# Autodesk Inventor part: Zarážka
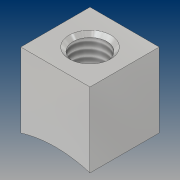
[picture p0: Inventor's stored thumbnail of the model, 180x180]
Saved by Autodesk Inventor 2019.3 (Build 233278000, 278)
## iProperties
Created: 2019-04
Part Number: Zarážka
Material: Hliník 6061-AHC
Document SubType Name: Modeling
Designer: B-hon
Density: 2.7 g/cm^3
Appearance: Hliník – tmavý
Author: B-hon
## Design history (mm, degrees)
sketch "Náčrt1"
  geometry: L1 (30, 0)-(30, 15); L2 (30, 15)-(0, 15); L3 (0, 15)-(0, 0); L4 (0, 0)-(2.958, 0); L5 (27.042, 0)-(30, 0); A1 r 17 centre (15, -12) between (27.042, 0) and (2.958, 0)
  constraints: 10 end point, 3 parallel, 2 horizontal, 2 perpendicular, 2 point on circle, 1 centre point
  dimensions: "d0" = 34 diameter of A1; "d1" = 30 distance of L1.end L2.end; "d2" = 15 distance from line of L3 A1.centre; "d4" = 15 distance of L2.end L3.end; "d16" = 12 distance from line of A1.centre L5
extrude "Vysunutí1" new body sketch "Náčrt1" distance "d5" = 10; taper "d6" = 0 deg
sketch "Náčrt2"
  geometry: L1 (0, 0)-(0, -10) reference; L2 (30, -10)-(0, -10) reference; 1 further point
  dimensions: "d14" = 15 distance from line of L1 point (15, -5); "d15" = 5 distance from line of L2 point (15, -5)
hole "Díra1" sketch "Náčrt2" at (15, -5) diameter "d7" = 4.917; stored, may be unused: countersink angle "d11" = 90 deg, drill point angle "d13" = 118 deg; dims "d8" = 12, "d9" = 6, "d10" = 2, "d12" = 17.1
sketch "Náčrt3"
  geometry: L1 (10, 16.649)-(20, 16.649); L2 (20, 16.649)-(20, 2.47); L3 (20, 2.47)-(10, 2.47); L4 (10, 2.47)-(10, 16.649); L5 (-7.417, 26.563)-(44.253, 26.563); L6 (44.253, 26.563)-(44.253, -14.738); L7 (44.253, -14.738)-(-7.417, -14.738); L8 (-7.417, -14.738)-(-7.417, 26.563); A1 r 17 centre (15, -12) between (27.042, 0) and (2.958, 0) reference; 1 further point
  constraints: 16 end point, 4 parallel, 2 horizontal, 2 perpendicular
  dimensions: "d17" = 5 distance from line of L2 A1.centre; "d18" = 5 distance from line of A1.centre L4 (= d17)
extrude "Vysunutí2" cut sketch "Náčrt3" distance "d19" = 10; taper "d20" = 0 deg
node "Těleso1"
other parameters: "d3" = 12
